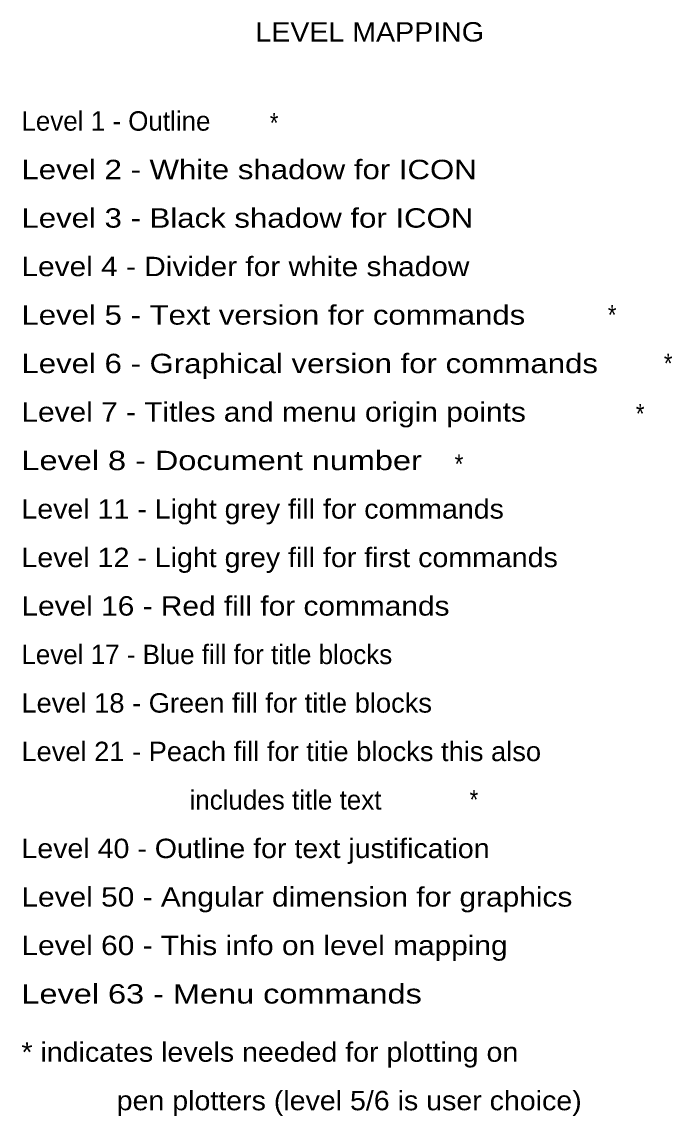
# Model space of a CAD drawing. Extents: x 95909.2 to 95923.3, y 90965 to 90971.2.
# Drawn here: x 95919.98 to 95923.32, y 90965.01 to 90970.65 of the extents above; entities that cross this region are included whole.
import ezdxf
from ezdxf.enums import TextEntityAlignment as Align

# ---------------------------------------------------------------- set-up
doc = ezdxf.new("R2010")
doc.units = 0
doc.header["$LTSCALE"] = 0.019
doc.layers.add('60', color=7, linetype='Continuous')

msp = doc.modelspace()

# ---------------------------------------------------------------- texts
at = {"layer": '60', "width": 1.1}
msp.add_text('LEVEL MAPPING', height=0.1, dxfattribs=at).set_placement((95921.7672, 90970.551), align=Align.CENTER)
at = {"layer": '60'}
for s, p in [('Level 1 - Outline', (95919.973, 90970.0916)), ('Level 17 - Blue fill for title blocks', (95919.973, 90967.3416)), ('includes title text', (95920.8389, 90966.5916))]:
    msp.add_text(s, height=0.1, dxfattribs=at).set_placement(p)
for s, width, p in [('*', 0.85, (95921.2526, 90970.082)), ('Level 2 - White shadow for ICON', 1.2, (95919.973, 90969.8416)), ('Level 3 - Black shadow for ICON', 1.2, (95919.973, 90969.5916)), ('Level 4 - Divider for white shadow', 1.15, (95919.973, 90969.3416)), ('Level 5 - Text version for commands', 1.2, (95919.973, 90969.0916)), ('*', 0.85, (95922.9939, 90969.0922)), ('Level 6 - Graphical version for commands', 1.2, (95919.973, 90968.8416)), ('*', 0.85, (95923.2825, 90968.8424)), ('Level 7 - Titles and menu origin points', 1.15, (95919.973, 90968.5916)), ('*', 0.85, (95923.1383, 90968.5828)), ('Level 8 - Document number', 1.25, (95919.973, 90968.3416)), ('*', 0.85, (95922.205, 90968.3234)), ('Level 11 - Light grey fill for commands', 1.1, (95919.973, 90968.0916)), ('Level 12 - Light grey fill for first commands', 1.1, (95919.973, 90967.8416)), ('Level 16 - Red fill for commands', 1.15, (95919.973, 90967.5916)), ('Level 18 - Green fill for title blocks', 1.05, (95919.973, 90967.0916)), ('Level 21 - Peach fill for titie blocks this also', 1.05, (95919.973, 90966.8416)), ('*', 0.85, (95922.282, 90966.5935)), ('Level 40 - Outline for text justification', 1.1, (95919.973, 90966.3416)), ('Level 50 - Angular dimension for graphics', 1.15, (95919.973, 90966.0916)), ('Level 60 - This info on level mapping', 1.15, (95919.973, 90965.8416)), ('Level 63 - Menu commands', 1.25, (95919.973, 90965.5916)), ('* indicates levels needed for plotting on ', 1.1, (95919.973, 90965.2916)), ('pen plotters (level 5/6 is user choice)', 1.1, (95920.4637, 90965.0416))]:
    msp.add_text(s, height=0.1, dxfattribs=dict(at, width=width)).set_placement(p)

doc.saveas('drawing.dxf')
